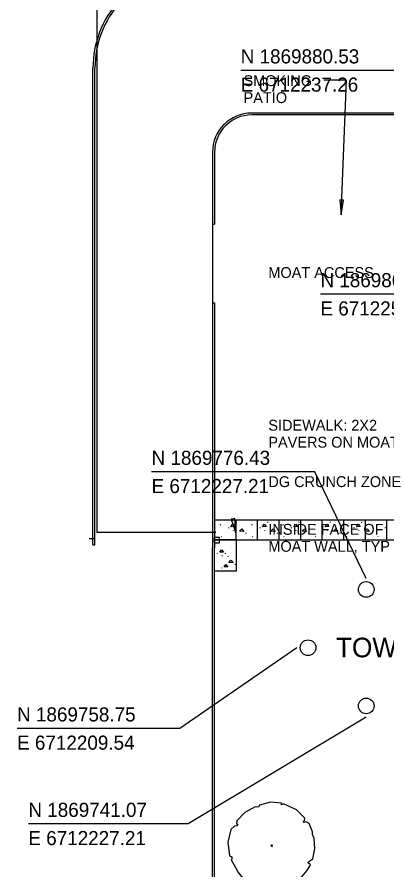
# Model space of a CAD drawing. Extents: x 6712138 to 6712574, y 1869536 to 1870160.
# Drawn here: x 6712138.1 to 6712232.5, y 1869702.1 to 1869919.6 of the extents above; entities that cross this region are included whole.
import ezdxf

# ---------------------------------------------------------------- set-up
doc = ezdxf.new("R2010")
doc.units = 0
for name, color, linetype in [('A-ANNO-TEXT', 7, 'Continuous'), ('A-DETL-LLIN', 7, 'Continuous'), ('A-FLOR-OTLN', 7, 'Continuous'), ('A-FLOR-PATT', 7, 'Continuous'), ('A-SECT-MBND', 7, 'Continuous'), ('C-Boun-Imaginary', 7, 'Continuous'), ('C-PRKG-CONC', 7, 'Continuous'), ('I-WALL', 7, 'Continuous'), ('L-SITE-PAVE', 7, 'Continuous'), ('L-tree', 7, 'Continuous')]:
    doc.layers.add(name, color=color, linetype=linetype)

# ---------------------------------------------------------------- blocks, each defined once
blk = doc.blocks.new('TREE 1')
at = {"layer": 'L-tree'}
for p, q in [((-0.027, 0.572), (-0.168, 0.532)), ((0.117, 0.559), (-0.027, 0.572)), ((0.117, 0.537), (0.117, 0.559)), ((-0.223, 0.51), (-0.357, 0.436)), ((-0.203, 0.506), (-0.223, 0.51)), ((-0.178, 0.51), (-0.203, 0.506)), ((-0.168, 0.532), (-0.178, 0.51)), ((0.144, 0.55), (0.117, 0.537)), ((0.312, 0.471), (0.144, 0.55)), ((0.419, 0.365), (0.312, 0.471)), ((-0.357, 0.436), (-0.46, 0.33)), ((0.398, 0.317), (0.415, 0.334)), ((0.415, 0.334), (0.419, 0.365)), ((-0.491, 0.26), (-0.539, 0.216)), ((-0.46, 0.264), (-0.491, 0.26)), ((-0.46, 0.33), (-0.467, 0.29)), ((-0.467, 0.29), (-0.45, 0.286)), ((-0.45, 0.286), (-0.46, 0.264)), ((0.408, 0.308), (0.398, 0.317)), ((0.436, 0.317), (0.408, 0.308)), ((0.474, 0.295), (0.436, 0.317)), ((0.518, 0.185), (0.474, 0.295)), ((-0.539, 0.216), (-0.577, 0.053)), ((0.518, 0.15), (0.518, 0.185)), ((0.542, 0.101), (0.518, 0.15)), ((-0.577, 0.053), (-0.559, -0.123)), ((-0.003, 0.018), (-0.021, 0.009)), ((-0.021, 0.009), (-0.014, 0)), ((-0.014, 0), (0, 0)), ((0, 0), (-0.003, 0.018)), ((0.549, -0.031), (0.542, 0.101)), ((0.525, -0.163), (0.549, -0.031)), ((-0.559, -0.123), (-0.529, -0.136)), ((-0.525, -0.163), (-0.535, -0.176)), ((-0.535, -0.176), (-0.439, -0.343)), ((-0.529, -0.136), (-0.525, -0.163)), ((0.463, -0.207), (0.484, -0.189)), ((0.47, -0.229), (0.463, -0.207)), ((0.484, -0.189), (0.525, -0.163)), ((0.381, -0.396), (0.446, -0.317)), ((0.446, -0.317), (0.494, -0.246)), ((0.484, -0.229), (0.47, -0.229)), ((0.494, -0.246), (0.484, -0.229)), ((-0.439, -0.343), (-0.384, -0.414)), ((-0.384, -0.414), (-0.295, -0.466)), ((0.244, -0.488), (0.381, -0.396)), ((-0.295, -0.466), (-0.281, -0.458)), ((-0.281, -0.458), (-0.261, -0.449)), ((-0.261, -0.449), (-0.247, -0.466)), ((-0.247, -0.466), (-0.199, -0.506)), ((-0.199, -0.506), (-0.137, -0.537)), ((-0.137, -0.537), (-0.017, -0.554)), ((-0.017, -0.554), (0.089, -0.546)), ((0.089, -0.546), (0.175, -0.524)), ((0.175, -0.524), (0.178, -0.506)), ((0.178, -0.506), (0.192, -0.488)), ((0.192, -0.488), (0.227, -0.484)), ((0.227, -0.484), (0.244, -0.488))]:
    blk.add_line(p, q, dxfattribs=at)

msp = doc.modelspace()

# ---------------------------------------------------------------- linework, layer by layer
at = {"layer": 'A-ANNO-TEXT'}
for p, q in [((6712217.79, 1869903.52), (6712216.4, 1869903.52)), ((6712217.79, 1869903.52), (6712216.4, 1869903.52)), ((6712222.18, 1869903.52), (6712217.79, 1869903.52)), ((6712222.18, 1869903.52), (6712217.79, 1869903.52)), ((6712220.79, 1869869.18), (6712222.18, 1869903.52)), ((6712220.79, 1869869.18), (6712222.18, 1869903.52)), ((6712221.43, 1869872.91), (6712220.44, 1869872.95)), ((6712220.44, 1869872.95), (6712220.79, 1869869.18)), ((6712221.43, 1869872.91), (6712220.44, 1869872.95)), ((6712220.44, 1869872.95), (6712220.79, 1869869.18)), ((6712221.43, 1869872.91), (6712220.44, 1869872.95)), ((6712220.44, 1869872.95), (6712220.79, 1869869.18)), ((6712221.43, 1869872.91), (6712220.44, 1869872.95)), ((6712220.44, 1869872.95), (6712220.79, 1869869.18)), ((6712220.79, 1869869.18), (6712221.43, 1869872.91)), ((6712220.79, 1869869.18), (6712221.43, 1869872.91)), ((6712220.79, 1869869.18), (6712221.43, 1869872.91)), ((6712220.79, 1869869.18), (6712221.43, 1869872.91)), ((6712193.7, 1869791.7), (6712192.73, 1869791.52)), ((6712193.7, 1869791.7), (6712192.73, 1869791.52)), ((6712192.73, 1869791.52), (6712193.92, 1869787.93)), ((6712192.73, 1869791.52), (6712193.92, 1869787.93)), ((6712193.92, 1869787.93), (6712193.7, 1869791.7)), ((6712193.92, 1869787.93), (6712193.7, 1869791.7))]:
    msp.add_line(p, q, dxfattribs=at)
at = {"layer": 'A-DETL-LLIN'}
for p, q in [((6712156.49, 1869786.56), (6712157.72, 1869786.56)), ((6712157.49, 1869785.01), (6712157.99, 1869785.01))]:
    msp.add_line(p, q, dxfattribs=at)
at = {"layer": 'A-FLOR-OTLN'}
for p, q in [((6712188.49, 1869791.27), (6712188.49, 1869786.27)), ((6712238.18, 1869791.27), (6712188.49, 1869791.27)), ((6712188.49, 1869786.27), (6712246.18, 1869786.27))]:
    msp.add_line(p, q, dxfattribs=at)
at = {"layer": 'A-FLOR-PATT'}
for p, q in [((6712194.07, 1869790.72), (6712194.07, 1869790.88)), ((6712202.07, 1869790.72), (6712202.07, 1869790.88)), ((6712210.07, 1869790.72), (6712210.07, 1869790.88)), ((6712218.07, 1869790.72), (6712218.07, 1869790.88)), ((6712226.07, 1869790.72), (6712226.07, 1869790.88)), ((6712190.09, 1869789.95), (6712190.05, 1869790.15)), ((6712192.11, 1869789.26), (6712192.11, 1869789.37)), ((6712193.32, 1869788.63), (6712193.36, 1869788.75)), ((6712198.08, 1869789.95), (6712198.04, 1869790.15)), ((6712200.11, 1869789.26), (6712200.11, 1869789.37)), ((6712201.32, 1869788.63), (6712201.36, 1869788.75)), ((6712206.08, 1869789.95), (6712206.04, 1869790.15)), ((6712208.11, 1869789.26), (6712208.11, 1869789.37)), ((6712209.32, 1869788.63), (6712209.36, 1869788.75)), ((6712214.08, 1869789.95), (6712214.04, 1869790.15)), ((6712216.11, 1869789.26), (6712216.11, 1869789.37)), ((6712217.32, 1869788.63), (6712217.36, 1869788.75)), ((6712222.08, 1869789.95), (6712222.04, 1869790.15)), ((6712224.11, 1869789.26), (6712224.11, 1869789.37)), ((6712225.32, 1869788.63), (6712225.36, 1869788.75)), ((6712230.08, 1869789.95), (6712230.04, 1869790.15)), ((6712232.11, 1869789.26), (6712232.11, 1869789.37)), ((6712190.29, 1869786.99), (6712190.21, 1869787.11)), ((6712196.59, 1869787.85), (6712196.59, 1869788.05)), ((6712198.28, 1869786.99), (6712198.2, 1869787.11)), ((6712204.59, 1869787.85), (6712204.59, 1869788.05)), ((6712206.28, 1869786.99), (6712206.2, 1869787.11)), ((6712212.59, 1869787.85), (6712212.59, 1869788.05)), ((6712214.28, 1869786.99), (6712214.2, 1869787.11)), ((6712220.59, 1869787.85), (6712220.59, 1869788.05)), ((6712222.28, 1869786.99), (6712222.2, 1869787.11)), ((6712228.59, 1869787.85), (6712228.59, 1869788.05)), ((6712230.28, 1869786.99), (6712230.2, 1869787.11)), ((6712189.23, 1869782.75), (6712189.23, 1869782.86)), ((6712190.44, 1869782.11), (6712190.48, 1869782.23)), ((6712191.32, 1869782.72), (6712191.32, 1869782.88)), ((6712192.04, 1869781.94), (6712191.96, 1869782.06)), ((6712193.84, 1869779.85), (6712193.84, 1869780.05)), ((6712190.36, 1869779.02), (6712190.36, 1869779.13)), ((6712191.58, 1869778.38), (6712191.62, 1869778.5))]:
    msp.add_line(p, q, dxfattribs=at)
for points in [[(6712192.7, 1869789.61), (6712193.13, 1869790.24), (6712193.64, 1869789.65)], [(6712194.89, 1869788.49), (6712195.45, 1869789.04), (6712195.99, 1869788.41)], [(6712200.7, 1869789.61), (6712201.13, 1869790.24), (6712201.64, 1869789.65)], [(6712202.89, 1869788.49), (6712203.45, 1869789.04), (6712203.99, 1869788.41)], [(6712208.7, 1869789.61), (6712209.13, 1869790.24), (6712209.64, 1869789.65)], [(6712210.89, 1869788.49), (6712211.45, 1869789.04), (6712211.99, 1869788.41)], [(6712216.7, 1869789.61), (6712217.13, 1869790.24), (6712217.64, 1869789.65)], [(6712218.89, 1869788.49), (6712219.45, 1869789.04), (6712219.99, 1869788.41)], [(6712224.7, 1869789.61), (6712225.13, 1869790.24), (6712225.64, 1869789.65)], [(6712226.89, 1869788.49), (6712227.45, 1869789.04), (6712227.99, 1869788.41)], [(6712189.82, 1869783.1), (6712190.25, 1869783.73), (6712190.76, 1869783.14)], [(6712190.95, 1869779.37), (6712191.38, 1869780), (6712191.89, 1869779.41)], [(6712192.14, 1869780.49), (6712192.7, 1869781.04), (6712193.24, 1869780.41)]]:
    msp.add_lwpolyline(points, close=True, dxfattribs=at)
at = {"layer": 'A-SECT-MBND'}
msp.add_lwpolyline([(6712188.44, 1869785.53), (6712189.78, 1869785.53), (6712189.78, 1869786.86), (6712188.44, 1869786.86)], close=True, dxfattribs=at)
at = {"layer": 'C-Boun-Imaginary'}
msp.add_lwpolyline([(6712158.49, 1869958.67), (6712158.49, 1869788.19), (6712188.82, 1869788.19)], dxfattribs=at)
at = {"layer": 'C-PRKG-CONC'}
for p, q in [((6712157.49, 1869851.97), (6712157.49, 1869906.6)), ((6712157.99, 1869851.97), (6712157.99, 1869906.6)), ((6712239.9, 1869895.11), (6712197.99, 1869895.11)), ((6712239.9, 1869894.61), (6712197.99, 1869894.61)), ((6712187.99, 1869885.11), (6712187.99, 1869866.74)), ((6712188.49, 1869885.11), (6712188.49, 1869866.74)), ((6712187.99, 1869866.74), (6712188.49, 1869866.74)), ((6712187.99, 1869866.74), (6712187.99, 1869846.74)), ((6712157.49, 1869825.31), (6712157.49, 1869851.97)), ((6712157.99, 1869825.31), (6712157.99, 1869851.97)), ((6712187.99, 1869846.74), (6712188.49, 1869846.74)), ((6712187.99, 1869846.74), (6712187.99, 1869785.01)), ((6712188.49, 1869846.74), (6712188.49, 1869785.01)), ((6712157.49, 1869785.01), (6712157.49, 1869825.31)), ((6712157.99, 1869785.01), (6712157.99, 1869825.31)), ((6712193.99, 1869786.27), (6712188.49, 1869786.27)), ((6712193.99, 1869786.27), (6712193.99, 1869778.27)), ((6712157.49, 1869785.01), (6712157.99, 1869785.01)), ((6712187.99, 1869785.01), (6712187.99, 1869784.19)), ((6712187.99, 1869658.41), (6712187.99, 1869784.19)), ((6712188.49, 1869785.01), (6712188.49, 1869784.19)), ((6712188.49, 1869658.43), (6712188.49, 1869784.19)), ((6712193.99, 1869778.27), (6712188.49, 1869778.27))]:
    msp.add_line(p, q, dxfattribs=at)
for centre, radius, start in [((6712182.99, 1869906.6), 25.5, 138.1293), ((6712182.99, 1869906.6), 25, 138.1293), ((6712197.99, 1869885.11), 10, 90), ((6712197.99, 1869885.11), 9.5, 90)]:
    msp.add_arc(centre, radius, start, 180, dxfattribs=at)
at = {"layer": 'I-WALL'}
for points in [[(6712237.26, 1869905.96), (6712195.18, 1869905.96)], [(6712257.26, 1869848.88), (6712215.52, 1869848.88)], [(6712214.06, 1869803.58), (6712172.44, 1869803.58)], [(6712227.21, 1869776.43), (6712214.06, 1869803.58)], [(6712209.54, 1869758.75), (6712179.66, 1869738.13)], [(6712227.21, 1869741.07), (6712181.76, 1869713.79)], [(6712179.66, 1869738.13), (6712138.12, 1869738.13)], [(6712181.76, 1869713.79), (6712141.01, 1869713.79)]]:
    msp.add_lwpolyline(points, dxfattribs=at)
for centre in [(6712227.21, 1869773.6), (6712212.36, 1869758.75), (6712227.21, 1869743.9)]:
    msp.add_circle(centre, 2, dxfattribs=at)
at = {"layer": 'L-SITE-PAVE'}
for p, q in [((6712188.49, 1869791.27), (6712188.49, 1869786.27)), ((6712193.99, 1869786.27), (6712193.99, 1869791.27)), ((6712199.49, 1869786.27), (6712199.49, 1869791.27)), ((6712204.99, 1869786.27), (6712204.99, 1869791.27)), ((6712210.49, 1869786.27), (6712210.49, 1869791.27)), ((6712215.99, 1869786.27), (6712215.99, 1869791.27)), ((6712221.49, 1869786.27), (6712221.49, 1869791.27)), ((6712226.99, 1869786.27), (6712226.99, 1869791.27)), ((6712232.49, 1869786.27), (6712232.49, 1869791.27)), ((6712193.99, 1869786.27), (6712188.49, 1869786.27)), ((6712188.49, 1869785.01), (6712188.49, 1869784.19)), ((6712188.49, 1869778.27), (6712188.49, 1869784.19))]:
    msp.add_line(p, q, dxfattribs=at)

# ---------------------------------------------------------------- block references
at = {"layer": 'L-tree', "xscale": 19.685038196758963, "yscale": 19.685039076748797}
msp.add_blockref('TREE 1', (6712203.29, 1869708.11), dxfattribs=at)

# ---------------------------------------------------------------- texts
at = {"layer": 'A-ANNO-TEXT'}
for s, height, p in [('SMOKING', 2.766, (6712195.91, 1869901.98)), ('SMOKING', 2.766, (6712195.91, 1869901.98)), ('PATIO', 2.766, (6712195.91, 1869897.65)), ('PATIO', 2.766, (6712195.91, 1869897.65)), ('MOAT ACCESS', 2.7662, (6712202.23, 1869853.04)), ('MOAT ACCESS', 2.7662, (6712202.23, 1869853.04)), ('SIDEWALK: 2X2', 2.7662, (6712202.23, 1869814.1)), ('SIDEWALK: 2X2', 2.7662, (6712202.23, 1869814.1)), ('PAVERS ON MOAT LID', 2.7662, (6712202.23, 1869809.77)), ('PAVERS ON MOAT LID', 2.7662, (6712202.23, 1869809.77)), ('DG CRUNCH ZONE', 2.7662, (6712202.23, 1869799.71)), ('DG CRUNCH ZONE', 2.7662, (6712202.23, 1869799.71)), ('INSIDE FACE OF', 2.7662, (6712202.23, 1869787.55)), ('INSIDE FACE OF', 2.7662, (6712202.23, 1869787.55)), ('MOAT WALL, TYP', 2.7662, (6712202.23, 1869783.22)), ('MOAT WALL, TYP', 2.7662, (6712202.23, 1869783.22))]:
    msp.add_text(s, height=height, dxfattribs=at).set_placement(p)
msp.add_text('TOWER', height=5, rotation=0.2528, dxfattribs=at).set_placement((6712219.5, 1869756.27))
at = {"layer": 'I-WALL'}
for s, p in [('N 1869880.53', (6712195.18, 1869907.76)), ('E 6712237.26', (6712195.18, 1869900.56)), ('N 1869860.53', (6712215.52, 1869850.68)), ('E 6712257.26', (6712215.52, 1869843.48)), ('N 1869776.43', (6712172.44, 1869805.38)), ('E 6712227.21', (6712172.44, 1869798.18)), ('N 1869758.75', (6712138.12, 1869739.93)), ('E 6712209.54', (6712138.12, 1869732.73)), ('N 1869741.07', (6712141.01, 1869715.59)), ('E 6712227.21', (6712141.01, 1869708.39))]:
    msp.add_text(s, height=3.6, dxfattribs=at).set_placement(p)

doc.saveas('drawing.dxf')
